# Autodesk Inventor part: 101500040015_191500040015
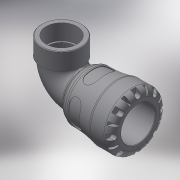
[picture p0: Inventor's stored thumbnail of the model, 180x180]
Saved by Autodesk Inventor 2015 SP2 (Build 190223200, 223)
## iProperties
Created: 2016-12
Part Number: 101500040015_191500040015
Material: Generic
Description: PLASSON 90° ELBOW WITH THREADED FEMALE OFFTAKE 40X1.1/2" SERIES 1
Document SubType Name: Modeling
Designer: KIM
Mass: 557.611 g
Surface Area: 990.043 cm^2
Volume: 557.611 cm^3
Density: 1 g/cm^3
Appearance: Default
Author: KIM
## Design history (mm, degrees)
derived "1015.ipt"
feature "Solid1::1015.ipt"
tag "TaggingFeature1"
body "Solid1"
other parameters: "d1" = 30.24, "d8" = 61.6, "d13" = 8, "d14" = 8, "d15" = 0, "d17" = 360 deg, "d19" = 8 deg, "d20" = 0.8, "d21" = 0.8, "d22" = 8 deg, "d24" = 0, "d26" = 360 deg, "d33" = 7, "d43" = 57.4, "d51" = 0.7, "d54" = 14, "d55" = 8.8, "d57" = 15.68, "d58" = 0, "d74" = 0, "d78" = 72, "d82" = 0.8, "d115" = 360 deg, "d207" = 90 deg, "d228" = 11.9, "d247" = 1.4, "d248" = 4.32, "d268" = 33.88, "d269" = 4.32, "d270" = 107, "d279" = 65, "d281" = 6.72675, "d294" = 44.845, "d295" = 24, "d296" = 26.4, "d297" = 40.3605, "d299" = 52.46865, "d300" = 40.3605, "d301" = 0, "d302" = 0, "d303" = 2.46568, "d306" = 0, "d307" = 9, "d308" = 8, "d310" = 3, "l_" = 72, "A_" = 107, "A_1" = 65, "l_2" = 24, "Rp_" = 44.845, "d298" = 58.2985
